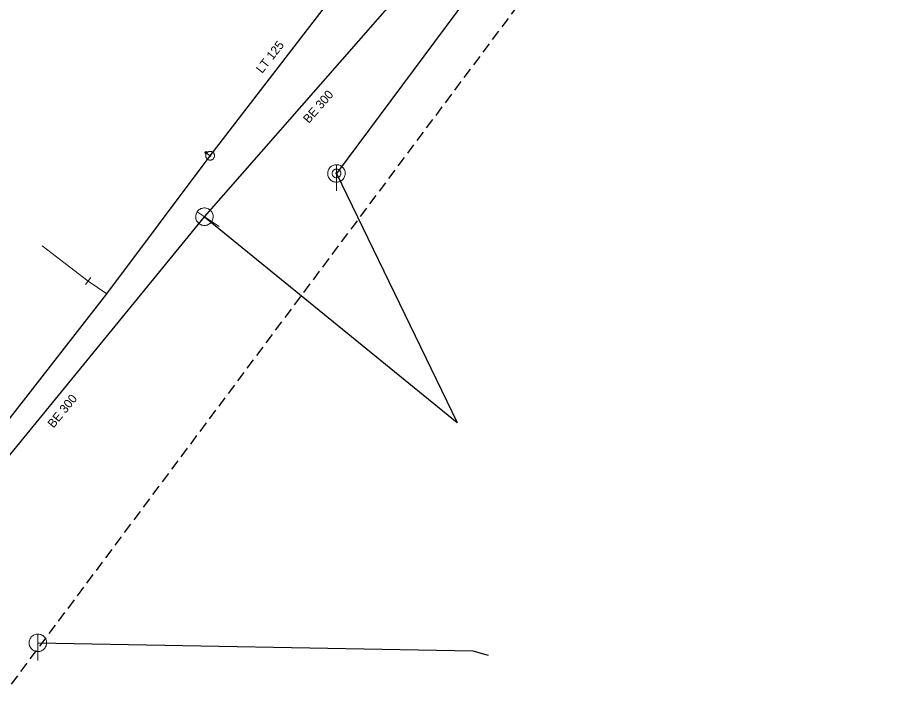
# Model space of a CAD drawing. Extents: x -791337 to -790755, y -988454 to -987923.
# Drawn here: x -790856.3 to -790755.1, y -988339.8 to -988262.8 of the extents above; entities that cross this region are included whole.
import ezdxf

# ---------------------------------------------------------------- set-up
doc = ezdxf.new("R2010")
doc.units = 0
doc.header["$LTSCALE"] = 0.4
doc.linetypes.add('MEDIUM_DASHED', pattern=[4.5, 3, -1.5])
for name, color, linetype, lineweight in [('1', 7, 'Continuous', 13), ('13', 7, 'Continuous', 13), ('14', 7, 'Continuous', 25), ('17', 7, 'Continuous', 25), ('22', 7, 'Continuous', 13), ('31', 7, 'Continuous', 13), ('34', 7, 'Continuous', 13), ('47', 7, 'Continuous', 13), ('63', 7, 'MEDIUM_DASHED', 25), ('9', 7, 'Continuous', 13)]:
    doc.layers.add(name, color=color, linetype=linetype, lineweight=lineweight)

msp = doc.modelspace()

# ---------------------------------------------------------------- linework, layer by layer
at = {"layer": '13'}
msp.add_lwpolyline([(-790846.136, -988294.261), (-790848.258, -988292.809), (-790853.495, -988288.793)], dxfattribs=at)
at = {"layer": '14'}
for p, q in [((-790768.42, -988211.39), (-790819.92, -988280.52)), ((-790834.989, -988285.46), (-790810.19, -988257.17)), ((-790819.92, -988280.52), (-790806.142, -988308.934)), ((-790834.989, -988285.46), (-790806.142, -988308.934))]:
    msp.add_line(p, q, dxfattribs=at)
at = {"layer": '14', "lineweight": 13}
msp.add_line((-790834.336, -988278.503), (-790834.799, -988278.159), dxfattribs=at)
at = {"layer": '14'}
for points in [[(-790891.652, -988309.185), (-790868.702, -988326.671), (-790834.989, -988285.46)], [(-790854, -988334.079), (-790804.338, -988335.011), (-790802.596, -988335.488)]]:
    msp.add_lwpolyline(points, dxfattribs=at)
at = {"layer": '17'}
msp.add_line((-790834.335, -988278.502), (-790817.244, -988256.29), dxfattribs=at)
msp.add_lwpolyline([(-790868.671, -988323.153), (-790846.136, -988294.261), (-790834.335, -988278.502)], dxfattribs=at)
at = {"layer": '22'}
for p, q in [((-790819.92, -988282.52), (-790819.919, -988279.52)), ((-790833.318, -988286.561), (-790835.823, -988284.909)), ((-790854, -988336.079), (-790853.999, -988333.079))]:
    msp.add_line(p, q, dxfattribs=at)
for points in [[(-790818.92, -988280.52), (-790818.925, -988280.411), (-790818.943, -988280.303), (-790818.973, -988280.197), (-790819.013, -988280.096), (-790819.065, -988279.999), (-790819.127, -988279.909), (-790819.199, -988279.826), (-790819.279, -988279.752), (-790819.367, -988279.686), (-790819.461, -988279.631), (-790819.561, -988279.586), (-790819.666, -988279.553), (-790819.773, -988279.531), (-790819.882, -988279.521), (-790819.992, -988279.523), (-790820.1, -988279.537), (-790820.207, -988279.562), (-790820.31, -988279.599), (-790820.408, -988279.648), (-790820.5, -988279.706), (-790820.586, -988279.775), (-790820.663, -988279.852), (-790820.732, -988279.938), (-790820.791, -988280.03), (-790820.839, -988280.128), (-790820.876, -988280.231), (-790820.902, -988280.338), (-790820.916, -988280.446), (-790820.919, -988280.556), (-790820.909, -988280.665), (-790820.888, -988280.772), (-790820.854, -988280.876), (-790820.81, -988280.976), (-790820.755, -988281.071), (-790820.689, -988281.159), (-790820.615, -988281.239), (-790820.532, -988281.311), (-790820.442, -988281.373), (-790820.346, -988281.425), (-790820.244, -988281.466), (-790820.139, -988281.496), (-790820.031, -988281.514), (-790819.921, -988281.52), (-790819.812, -988281.514), (-790819.704, -988281.496), (-790819.599, -988281.467), (-790819.497, -988281.426), (-790819.4, -988281.374), (-790819.31, -988281.312), (-790819.227, -988281.241), (-790819.152, -988281.161), (-790819.087, -988281.073), (-790819.031, -988280.979), (-790818.987, -988280.879), (-790818.953, -988280.775), (-790818.931, -988280.667), (-790818.921, -988280.558)], [(-790834.438, -988284.625), (-790834.532, -988284.57), (-790834.632, -988284.525), (-790834.737, -988284.492), (-790834.843, -988284.47), (-790834.953, -988284.46), (-790835.062, -988284.462), (-790835.171, -988284.477), (-790835.277, -988284.503), (-790835.381, -988284.54), (-790835.478, -988284.588), (-790835.571, -988284.647), (-790835.656, -988284.716), (-790835.733, -988284.793), (-790835.802, -988284.879), (-790835.861, -988284.972), (-790835.908, -988285.07), (-790835.946, -988285.173), (-790835.972, -988285.279), (-790835.985, -988285.388), (-790835.987, -988285.497), (-790835.977, -988285.607), (-790835.955, -988285.713), (-790835.921, -988285.818), (-790835.877, -988285.918), (-790835.822, -988286.012), (-790835.756, -988286.1), (-790835.681, -988286.18), (-790835.599, -988286.251), (-790835.508, -988286.314), (-790835.411, -988286.365), (-790835.311, -988286.407), (-790835.205, -988286.436), (-790835.097, -988286.454), (-790834.988, -988286.46), (-790834.878, -988286.454), (-790834.77, -988286.436), (-790834.665, -988286.406), (-790834.563, -988286.365), (-790834.467, -988286.314), (-790834.377, -988286.251), (-790834.294, -988286.18), (-790834.219, -988286.1), (-790834.154, -988286.011), (-790834.099, -988285.917), (-790834.054, -988285.817), (-790834.021, -988285.713), (-790833.999, -988285.605), (-790833.989, -988285.496), (-790833.991, -988285.386), (-790834.005, -988285.278), (-790834.03, -988285.171), (-790834.068, -988285.069), (-790834.116, -988284.97), (-790834.175, -988284.878), (-790834.243, -988284.793), (-790834.321, -988284.715), (-790834.406, -988284.647)], [(-790853, -988334.079), (-790853.005, -988333.97), (-790853.023, -988333.862), (-790853.053, -988333.756), (-790853.093, -988333.655), (-790853.145, -988333.558), (-790853.207, -988333.468), (-790853.279, -988333.385), (-790853.359, -988333.311), (-790853.447, -988333.245), (-790853.541, -988333.19), (-790853.641, -988333.145), (-790853.746, -988333.112), (-790853.853, -988333.09), (-790853.962, -988333.08), (-790854.072, -988333.082), (-790854.18, -988333.096), (-790854.287, -988333.121), (-790854.39, -988333.158), (-790854.488, -988333.207), (-790854.58, -988333.265), (-790854.666, -988333.334), (-790854.743, -988333.411), (-790854.812, -988333.497), (-790854.871, -988333.589), (-790854.919, -988333.687), (-790854.956, -988333.79), (-790854.982, -988333.897), (-790854.996, -988334.005), (-790854.999, -988334.115), (-790854.989, -988334.224), (-790854.968, -988334.331), (-790854.934, -988334.435), (-790854.89, -988334.535), (-790854.835, -988334.63), (-790854.769, -988334.718), (-790854.695, -988334.798), (-790854.612, -988334.87), (-790854.522, -988334.932), (-790854.426, -988334.984), (-790854.324, -988335.025), (-790854.219, -988335.055), (-790854.111, -988335.073), (-790854.001, -988335.079), (-790853.892, -988335.073), (-790853.784, -988335.055), (-790853.679, -988335.026), (-790853.577, -988334.985), (-790853.48, -988334.933), (-790853.39, -988334.871), (-790853.307, -988334.8), (-790853.232, -988334.72), (-790853.167, -988334.632), (-790853.111, -988334.538), (-790853.067, -988334.438), (-790853.033, -988334.334), (-790853.011, -988334.226), (-790853.001, -988334.117)]]:
    msp.add_lwpolyline(points, close=True, dxfattribs=at)
at = {"layer": '31'}
for points in [[(-790819.683, -988280.96), (-790819.639, -988280.933), (-790819.597, -988280.901), (-790819.559, -988280.866), (-790819.525, -988280.827), (-790819.495, -988280.783), (-790819.47, -988280.737), (-790819.45, -988280.689), (-790819.435, -988280.639), (-790819.425, -988280.588), (-790819.42, -988280.535), (-790819.421, -988280.483), (-790819.428, -988280.431), (-790819.439, -988280.38), (-790819.457, -988280.331), (-790819.479, -988280.283), (-790819.506, -988280.239), (-790819.538, -988280.197), (-790819.574, -988280.159), (-790819.612, -988280.125), (-790819.656, -988280.095), (-790819.702, -988280.07), (-790819.751, -988280.049), (-790819.801, -988280.034), (-790819.852, -988280.024), (-790819.904, -988280.02), (-790819.956, -988280.021), (-790820.008, -988280.027), (-790820.059, -988280.039), (-790820.108, -988280.057), (-790820.156, -988280.079), (-790820.2, -988280.106), (-790820.242, -988280.138), (-790820.281, -988280.173), (-790820.314, -988280.212), (-790820.344, -988280.256), (-790820.37, -988280.301), (-790820.39, -988280.35), (-790820.406, -988280.4), (-790820.415, -988280.452), (-790820.419, -988280.504), (-790820.418, -988280.556), (-790820.412, -988280.608), (-790820.4, -988280.659), (-790820.382, -988280.708), (-790820.36, -988280.756), (-790820.333, -988280.8), (-790820.301, -988280.842), (-790820.266, -988280.88), (-790820.227, -988280.914), (-790820.183, -988280.944), (-790820.138, -988280.97), (-790820.09, -988280.99), (-790820.04, -988281.005), (-790819.988, -988281.014), (-790819.935, -988281.019), (-790819.883, -988281.018), (-790819.832, -988281.011), (-790819.78, -988281), (-790819.731, -988280.982)], [(-790819.881, -988280.592), (-790819.873, -988280.588), (-790819.867, -988280.582), (-790819.861, -988280.576), (-790819.855, -988280.57), (-790819.85, -988280.563), (-790819.846, -988280.555), (-790819.842, -988280.547), (-790819.84, -988280.539), (-790819.839, -988280.531), (-790819.838, -988280.522), (-790819.838, -988280.513), (-790819.839, -988280.505), (-790819.841, -988280.497), (-790819.843, -988280.489), (-790819.847, -988280.481), (-790819.851, -988280.473), (-790819.857, -988280.467), (-790819.863, -988280.461), (-790819.869, -988280.455), (-790819.876, -988280.45), (-790819.884, -988280.446), (-790819.892, -988280.442), (-790819.9, -988280.44), (-790819.909, -988280.438), (-790819.917, -988280.438), (-790819.926, -988280.438), (-790819.934, -988280.439), (-790819.942, -988280.441), (-790819.95, -988280.443), (-790819.958, -988280.447), (-790819.966, -988280.451), (-790819.972, -988280.457), (-790819.978, -988280.463), (-790819.984, -988280.469), (-790819.989, -988280.476), (-790819.993, -988280.483), (-790819.997, -988280.492), (-790819.999, -988280.5), (-790820.001, -988280.509), (-790820.001, -988280.517), (-790820.001, -988280.526), (-790820, -988280.534), (-790819.998, -988280.542), (-790819.996, -988280.55), (-790819.992, -988280.558), (-790819.988, -988280.566), (-790819.982, -988280.572), (-790819.976, -988280.578), (-790819.97, -988280.584), (-790819.963, -988280.589), (-790819.956, -988280.593), (-790819.947, -988280.597), (-790819.939, -988280.599), (-790819.931, -988280.6), (-790819.922, -988280.601), (-790819.913, -988280.601), (-790819.905, -988280.6), (-790819.897, -988280.598), (-790819.889, -988280.596)]]:
    msp.add_lwpolyline(points, close=True, dxfattribs=at)
at = {"layer": '34'}
msp.add_line((-790847.958, -988292.408), (-790848.557, -988293.209), dxfattribs=at)
at = {"layer": '47'}
for points in [[(-790833.836, -988278.503), (-790833.839, -988278.451), (-790833.847, -988278.399), (-790833.861, -988278.349), (-790833.879, -988278.3), (-790833.903, -988278.253), (-790833.932, -988278.209), (-790833.965, -988278.169), (-790834.002, -988278.132), (-790834.042, -988278.099), (-790834.086, -988278.07), (-790834.133, -988278.046), (-790834.182, -988278.028), (-790834.232, -988278.014), (-790834.284, -988278.006), (-790834.336, -988278.003), (-790834.388, -988278.006), (-790834.44, -988278.014), (-790834.491, -988278.028), (-790834.539, -988278.046), (-790834.586, -988278.07), (-790834.63, -988278.099), (-790834.671, -988278.132), (-790834.708, -988278.169), (-790834.741, -988278.209), (-790834.769, -988278.253), (-790834.793, -988278.3), (-790834.812, -988278.349), (-790834.825, -988278.399), (-790834.833, -988278.451), (-790834.836, -988278.503), (-790834.833, -988278.555), (-790834.825, -988278.607), (-790834.812, -988278.658), (-790834.793, -988278.706), (-790834.769, -988278.753), (-790834.741, -988278.797), (-790834.708, -988278.838), (-790834.671, -988278.875), (-790834.63, -988278.908), (-790834.586, -988278.936), (-790834.539, -988278.96), (-790834.491, -988278.979), (-790834.44, -988278.992), (-790834.388, -988279), (-790834.336, -988279.003), (-790834.284, -988279), (-790834.232, -988278.992), (-790834.182, -988278.979), (-790834.133, -988278.96), (-790834.086, -988278.936), (-790834.042, -988278.908), (-790834.002, -988278.875), (-790833.965, -988278.838), (-790833.932, -988278.797), (-790833.903, -988278.753), (-790833.879, -988278.706), (-790833.861, -988278.658), (-790833.847, -988278.607), (-790833.839, -988278.555)], [(-790834.254, -988278.503), (-790834.254, -988278.494), (-790834.256, -988278.486), (-790834.258, -988278.478), (-790834.261, -988278.47), (-790834.265, -988278.462), (-790834.27, -988278.455), (-790834.275, -988278.448), (-790834.281, -988278.442), (-790834.288, -988278.437), (-790834.295, -988278.432), (-790834.303, -988278.428), (-790834.311, -988278.425), (-790834.319, -988278.423), (-790834.327, -988278.421), (-790834.336, -988278.421), (-790834.345, -988278.421), (-790834.353, -988278.423), (-790834.361, -988278.425), (-790834.369, -988278.428), (-790834.377, -988278.432), (-790834.384, -988278.437), (-790834.391, -988278.442), (-790834.397, -988278.448), (-790834.403, -988278.455), (-790834.407, -988278.462), (-790834.411, -988278.47), (-790834.414, -988278.478), (-790834.416, -988278.486), (-790834.418, -988278.494), (-790834.418, -988278.503), (-790834.418, -988278.512), (-790834.416, -988278.52), (-790834.414, -988278.528), (-790834.411, -988278.536), (-790834.407, -988278.544), (-790834.403, -988278.551), (-790834.397, -988278.558), (-790834.391, -988278.564), (-790834.384, -988278.57), (-790834.377, -988278.574), (-790834.369, -988278.578), (-790834.361, -988278.581), (-790834.353, -988278.583), (-790834.345, -988278.585), (-790834.336, -988278.585), (-790834.327, -988278.585), (-790834.319, -988278.583), (-790834.311, -988278.581), (-790834.303, -988278.578), (-790834.295, -988278.574), (-790834.288, -988278.57), (-790834.281, -988278.564), (-790834.275, -988278.558), (-790834.27, -988278.551), (-790834.265, -988278.544), (-790834.261, -988278.536), (-790834.258, -988278.528), (-790834.256, -988278.52), (-790834.254, -988278.512)]]:
    msp.add_lwpolyline(points, close=True, dxfattribs=at)
at = {"layer": '63'}
msp.add_lwpolyline([(-791231.02, -987923.132), (-790755.118, -988202.253), (-790755.118, -988202.253), (-790903.053, -988400.429), (-790903.053, -988400.429), (-791331.504, -988073.857), (-791331.504, -988073.857)], close=True, dxfattribs=at)
at = {"layer": '9'}
for points in [[(-790834.924, -988278.159), (-790834.924, -988278.172), (-790834.921, -988278.185), (-790834.919, -988278.198), (-790834.914, -988278.21), (-790834.907, -988278.222), (-790834.901, -988278.233), (-790834.892, -988278.243), (-790834.882, -988278.253), (-790834.872, -988278.261), (-790834.862, -988278.268), (-790834.85, -988278.274), (-790834.838, -988278.279), (-790834.825, -988278.282), (-790834.811, -988278.284), (-790834.799, -988278.286), (-790834.786, -988278.285), (-790834.772, -988278.283), (-790834.76, -988278.28), (-790834.747, -988278.275), (-790834.735, -988278.269), (-790834.725, -988278.262), (-790834.715, -988278.254), (-790834.705, -988278.244), (-790834.696, -988278.234), (-790834.69, -988278.223), (-790834.684, -988278.211), (-790834.679, -988278.199), (-790834.676, -988278.186), (-790834.674, -988278.173), (-790834.671, -988278.16), (-790834.673, -988278.147), (-790834.674, -988278.134), (-790834.678, -988278.121), (-790834.683, -988278.109), (-790834.688, -988278.097), (-790834.696, -988278.086), (-790834.703, -988278.076), (-790834.713, -988278.066), (-790834.723, -988278.058), (-790834.735, -988278.051), (-790834.747, -988278.045), (-790834.759, -988278.04), (-790834.772, -988278.037), (-790834.784, -988278.035), (-790834.798, -988278.034), (-790834.811, -988278.034), (-790834.823, -988278.036), (-790834.837, -988278.039), (-790834.848, -988278.044), (-790834.86, -988278.05), (-790834.872, -988278.057), (-790834.882, -988278.065), (-790834.892, -988278.075), (-790834.899, -988278.085), (-790834.907, -988278.096), (-790834.913, -988278.108), (-790834.918, -988278.12), (-790834.921, -988278.133), (-790834.923, -988278.146)], [(-790834.904, -988278.159), (-790834.904, -988278.17), (-790834.902, -988278.181), (-790834.899, -988278.192), (-790834.896, -988278.202), (-790834.891, -988278.212), (-790834.885, -988278.221), (-790834.877, -988278.23), (-790834.87, -988278.238), (-790834.86, -988278.245), (-790834.852, -988278.251), (-790834.842, -988278.256), (-790834.831, -988278.26), (-790834.821, -988278.263), (-790834.809, -988278.266), (-790834.799, -988278.266), (-790834.788, -988278.266), (-790834.777, -988278.264), (-790834.766, -988278.261), (-790834.755, -988278.257), (-790834.745, -988278.252), (-790834.737, -988278.246), (-790834.728, -988278.239), (-790834.72, -988278.231), (-790834.713, -988278.222), (-790834.706, -988278.213), (-790834.701, -988278.203), (-790834.698, -988278.193), (-790834.695, -988278.182), (-790834.693, -988278.171), (-790834.691, -988278.16), (-790834.691, -988278.149), (-790834.693, -988278.138), (-790834.696, -988278.127), (-790834.701, -988278.117), (-790834.706, -988278.107), (-790834.712, -988278.098), (-790834.718, -988278.089), (-790834.727, -988278.081), (-790834.735, -988278.074), (-790834.745, -988278.068), (-790834.755, -988278.063), (-790834.764, -988278.059), (-790834.776, -988278.056), (-790834.786, -988278.054), (-790834.798, -988278.054), (-790834.809, -988278.053), (-790834.82, -988278.055), (-790834.831, -988278.058), (-790834.84, -988278.062), (-790834.85, -988278.067), (-790834.86, -988278.073), (-790834.869, -988278.08), (-790834.877, -988278.088), (-790834.884, -988278.097), (-790834.889, -988278.106), (-790834.894, -988278.116), (-790834.899, -988278.126), (-790834.902, -988278.137), (-790834.904, -988278.148)], [(-790834.885, -988278.159), (-790834.885, -988278.168), (-790834.884, -988278.177), (-790834.88, -988278.186), (-790834.877, -988278.194), (-790834.874, -988278.202), (-790834.869, -988278.21), (-790834.862, -988278.217), (-790834.857, -988278.223), (-790834.85, -988278.229), (-790834.842, -988278.234), (-790834.833, -988278.238), (-790834.826, -988278.241), (-790834.816, -988278.244), (-790834.808, -988278.245), (-790834.799, -988278.247), (-790834.789, -988278.246), (-790834.781, -988278.245), (-790834.772, -988278.242), (-790834.764, -988278.239), (-790834.755, -988278.235), (-790834.747, -988278.23), (-790834.74, -988278.224), (-790834.735, -988278.218), (-790834.728, -988278.211), (-790834.723, -988278.203), (-790834.72, -988278.195), (-790834.717, -988278.187), (-790834.713, -988278.178), (-790834.713, -988278.169), (-790834.71, -988278.16), (-790834.712, -988278.151), (-790834.713, -988278.142), (-790834.715, -988278.133), (-790834.718, -988278.125), (-790834.723, -988278.117), (-790834.728, -988278.109), (-790834.733, -988278.102), (-790834.74, -988278.096), (-790834.747, -988278.09), (-790834.755, -988278.085), (-790834.762, -988278.081), (-790834.771, -988278.078), (-790834.779, -988278.075), (-790834.789, -988278.074), (-790834.798, -988278.073), (-790834.806, -988278.073), (-790834.816, -988278.074), (-790834.825, -988278.077), (-790834.833, -988278.08), (-790834.84, -988278.084), (-790834.848, -988278.089), (-790834.855, -988278.095), (-790834.862, -988278.101), (-790834.867, -988278.108), (-790834.872, -988278.116), (-790834.877, -988278.124), (-790834.88, -988278.132), (-790834.882, -988278.141), (-790834.884, -988278.15)], [(-790834.865, -988278.159), (-790834.865, -988278.166), (-790834.864, -988278.173), (-790834.862, -988278.18), (-790834.86, -988278.186), (-790834.857, -988278.192), (-790834.853, -988278.198), (-790834.848, -988278.204), (-790834.843, -988278.209), (-790834.838, -988278.213), (-790834.831, -988278.217), (-790834.826, -988278.22), (-790834.82, -988278.223), (-790834.813, -988278.224), (-790834.806, -988278.227), (-790834.799, -988278.227), (-790834.791, -988278.227), (-790834.784, -988278.225), (-790834.777, -988278.224), (-790834.772, -988278.221), (-790834.764, -988278.218), (-790834.76, -988278.214), (-790834.754, -988278.21), (-790834.749, -988278.205), (-790834.745, -988278.199), (-790834.74, -988278.193), (-790834.737, -988278.187), (-790834.735, -988278.181), (-790834.733, -988278.174), (-790834.732, -988278.167), (-790834.73, -988278.16), (-790834.73, -988278.153), (-790834.732, -988278.146), (-790834.733, -988278.139), (-790834.737, -988278.133), (-790834.74, -988278.126), (-790834.744, -988278.121), (-790834.747, -988278.115), (-790834.752, -988278.11), (-790834.759, -988278.106), (-790834.764, -988278.102), (-790834.771, -988278.099), (-790834.777, -988278.096), (-790834.784, -988278.094), (-790834.791, -988278.093), (-790834.798, -988278.093), (-790834.804, -988278.093), (-790834.811, -988278.093), (-790834.818, -988278.095), (-790834.825, -988278.098), (-790834.831, -988278.101), (-790834.837, -988278.105), (-790834.843, -988278.109), (-790834.848, -988278.114), (-790834.852, -988278.12), (-790834.855, -988278.125), (-790834.858, -988278.132), (-790834.862, -988278.138), (-790834.862, -988278.145), (-790834.865, -988278.152)], [(-790834.845, -988278.159), (-790834.845, -988278.164), (-790834.845, -988278.169), (-790834.843, -988278.174), (-790834.842, -988278.178), (-790834.84, -988278.183), (-790834.837, -988278.187), (-790834.833, -988278.19), (-790834.83, -988278.194), (-790834.826, -988278.197), (-790834.823, -988278.2), (-790834.818, -988278.202), (-790834.813, -988278.204), (-790834.809, -988278.205), (-790834.804, -988278.207), (-790834.799, -988278.207), (-790834.794, -988278.207), (-790834.789, -988278.206), (-790834.784, -988278.205), (-790834.779, -988278.203), (-790834.774, -988278.201), (-790834.771, -988278.198), (-790834.767, -988278.195), (-790834.764, -988278.191), (-790834.761, -988278.188), (-790834.757, -988278.184), (-790834.755, -988278.179), (-790834.754, -988278.175), (-790834.752, -988278.17), (-790834.752, -988278.165), (-790834.75, -988278.16), (-790834.75, -988278.155), (-790834.752, -988278.15), (-790834.752, -988278.145), (-790834.755, -988278.141), (-790834.757, -988278.136), (-790834.76, -988278.132), (-790834.762, -988278.128), (-790834.766, -988278.125), (-790834.769, -988278.122), (-790834.774, -988278.119), (-790834.779, -988278.117), (-790834.782, -988278.115), (-790834.788, -988278.114), (-790834.793, -988278.113), (-790834.798, -988278.113), (-790834.803, -988278.113), (-790834.808, -988278.114), (-790834.813, -988278.114), (-790834.816, -988278.116), (-790834.821, -988278.118), (-790834.826, -988278.121), (-790834.828, -988278.124), (-790834.833, -988278.127), (-790834.835, -988278.131), (-790834.838, -988278.135), (-790834.84, -988278.14), (-790834.843, -988278.144), (-790834.843, -988278.149), (-790834.845, -988278.154)], [(-790834.825, -988278.159), (-790834.825, -988278.162), (-790834.826, -988278.165), (-790834.825, -988278.167), (-790834.823, -988278.17), (-790834.823, -988278.173), (-790834.821, -988278.175), (-790834.818, -988278.177), (-790834.816, -988278.179), (-790834.815, -988278.181), (-790834.813, -988278.183), (-790834.809, -988278.185), (-790834.806, -988278.186), (-790834.804, -988278.186), (-790834.801, -988278.187), (-790834.799, -988278.187), (-790834.796, -988278.187), (-790834.793, -988278.187), (-790834.789, -988278.186), (-790834.788, -988278.185), (-790834.784, -988278.184), (-790834.782, -988278.182), (-790834.779, -988278.18), (-790834.777, -988278.178), (-790834.777, -988278.176), (-790834.774, -988278.174), (-790834.774, -988278.171), (-790834.772, -988278.168), (-790834.772, -988278.166), (-790834.771, -988278.163), (-790834.769, -988278.16), (-790834.771, -988278.157), (-790834.771, -988278.154), (-790834.772, -988278.151), (-790834.772, -988278.149), (-790834.774, -988278.146), (-790834.776, -988278.144), (-790834.777, -988278.141), (-790834.779, -988278.139), (-790834.782, -988278.138), (-790834.784, -988278.136), (-790834.786, -988278.135), (-790834.789, -988278.134), (-790834.791, -988278.133), (-790834.794, -988278.133), (-790834.798, -988278.132), (-790834.801, -988278.133), (-790834.804, -988278.132), (-790834.806, -988278.134), (-790834.809, -988278.134), (-790834.811, -988278.135), (-790834.813, -988278.137), (-790834.816, -988278.138), (-790834.818, -988278.14), (-790834.82, -988278.143), (-790834.821, -988278.145), (-790834.823, -988278.148), (-790834.823, -988278.15), (-790834.825, -988278.153), (-790834.825, -988278.156)], [(-790834.806, -988278.159), (-790834.806, -988278.161), (-790834.806, -988278.161), (-790834.804, -988278.161), (-790834.804, -988278.163), (-790834.806, -988278.164), (-790834.804, -988278.164), (-790834.804, -988278.164), (-790834.804, -988278.166), (-790834.804, -988278.166), (-790834.803, -988278.167), (-790834.801, -988278.167), (-790834.801, -988278.167), (-790834.801, -988278.168), (-790834.799, -988278.168), (-790834.799, -988278.168), (-790834.798, -988278.168), (-790834.796, -988278.168), (-790834.796, -988278.167), (-790834.796, -988278.167), (-790834.794, -988278.167), (-790834.794, -988278.166), (-790834.794, -988278.166), (-790834.793, -988278.165), (-790834.793, -988278.165), (-790834.791, -988278.164), (-790834.791, -988278.163), (-790834.789, -988278.162), (-790834.789, -988278.162), (-790834.789, -988278.161), (-790834.789, -988278.16), (-790834.789, -988278.159), (-790834.789, -988278.158), (-790834.789, -988278.158), (-790834.791, -988278.157), (-790834.791, -988278.156), (-790834.791, -988278.155), (-790834.791, -988278.155), (-790834.793, -988278.154), (-790834.793, -988278.154), (-790834.794, -988278.153), (-790834.794, -988278.153), (-790834.796, -988278.152), (-790834.796, -988278.152), (-790834.796, -988278.152), (-790834.798, -988278.152), (-790834.799, -988278.152), (-790834.799, -988278.152), (-790834.799, -988278.152), (-790834.801, -988278.153), (-790834.801, -988278.152), (-790834.803, -988278.154), (-790834.803, -988278.154), (-790834.804, -988278.154), (-790834.804, -988278.154), (-790834.804, -988278.156), (-790834.804, -988278.157), (-790834.804, -988278.158), (-790834.806, -988278.158), (-790834.806, -988278.159)]]:
    msp.add_lwpolyline(points, close=True, dxfattribs=at)

# ---------------------------------------------------------------- texts
at = {"layer": '1'}
for s, rotation, p in [('LT 125', 52, (-790828.4, -988269.172)), ('BE 300', 49, (-790823.074, -988274.879)), ('BE 300', 51, (-790852.208, -988309.644))]:
    msp.add_text(s, height=1, rotation=rotation, dxfattribs=at).set_placement(p)

doc.saveas('drawing.dxf')
